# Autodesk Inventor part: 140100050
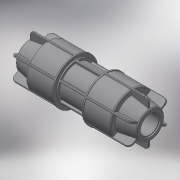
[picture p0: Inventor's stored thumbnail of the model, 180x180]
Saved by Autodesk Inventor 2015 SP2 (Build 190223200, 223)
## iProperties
Created: 2018-02
Part Number: 140100050
Material: Generic
Description: PLASSON L.14 COUPLER (SILVER) 50
Document SubType Name: Modeling
Designer: KIM
Mass: 472.555 g
Surface Area: 792.166 cm^2
Volume: 472.555 cm^3
Density: 1 g/cm^3
Appearance: Default
Author: KIM
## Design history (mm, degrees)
derived "140100.ipt"
feature "Solid1::140100.ipt"
tag "TaggingFeature1"
body "Solid1"
other parameters: "d30" = 1, "d36" = 1.46, "d65" = 89.24, "d77" = 46, "d95" = 21.9, "d96" = 1.46, "d97" = 55, "d100" = 69, "d102" = 55.48, "d103" = 1.46, "d107" = 62.65, "d113" = 92, "d114" = 5, "d115" = 2.5, "d117" = 0, "d126" = 9.2, "d127" = 0.92, "d129" = 360 deg, "d131" = 1.46, "d132" = 92, "d138" = 100 deg, "d139" = 78.2, "d141" = 146, "d143" = 71, "d144" = 0, "d146" = 71, "d147" = 0, "d149" = 4.6, "d150" = 2.3, "d152" = 0, "d153" = 0.92, "d155" = 360 deg, "E_" = 92, "l_" = 71, "H_" = 146
